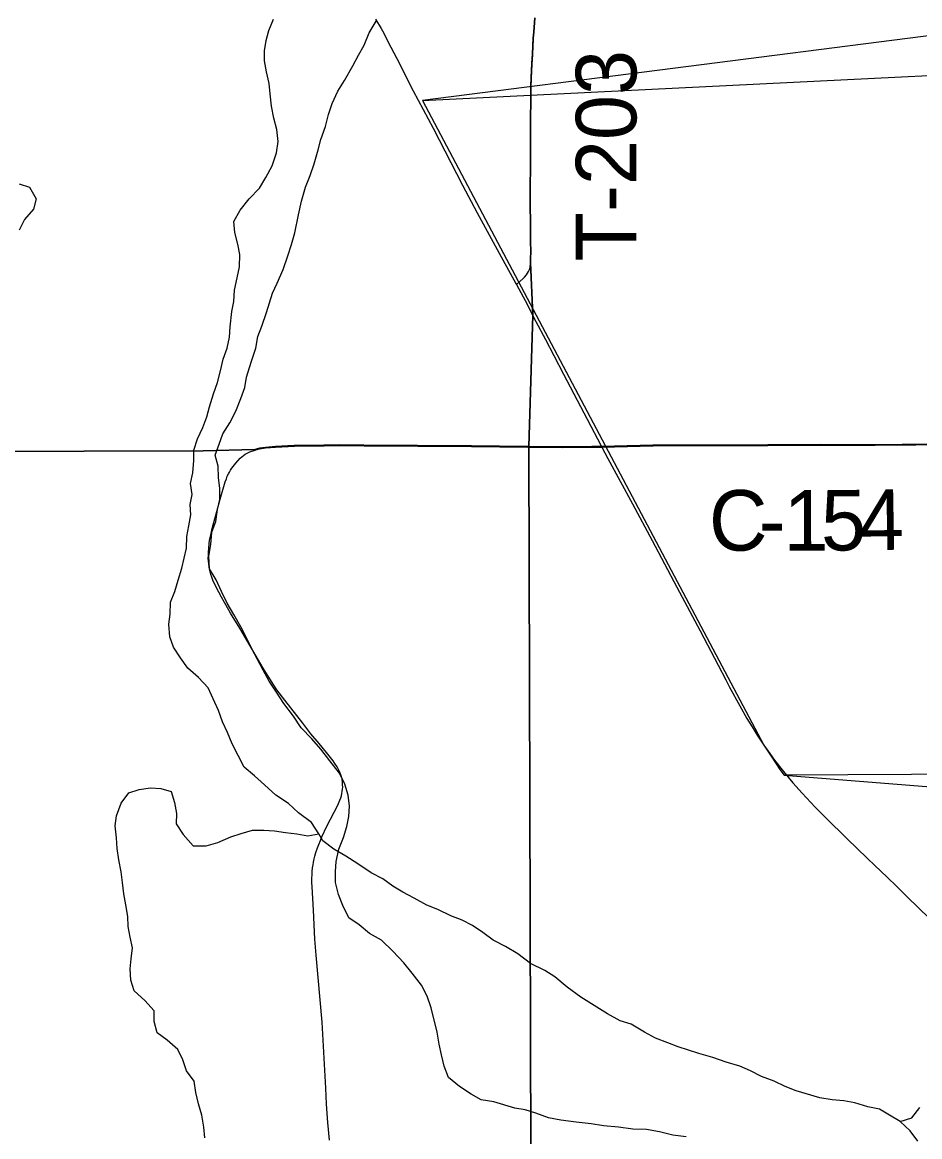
# Model space of a CAD drawing. Extents: x 0 to 34, y 0 to 22.
# Drawn here: x 4.562 to 5.404, y 16.57 to 17.616 of the extents above; entities that cross this region are included whole.
import ezdxf

# ---------------------------------------------------------------- set-up
doc = ezdxf.new("R2010")
doc.units = 0
for name, color, linetype in [('GM_X_Corporation', 7, 'Continuous'), ('GM_X_County_Road', 7, 'Continuous'), ('GM_X_County_Road_Text', 7, 'Continuous'), ('GM_X_Major_Lake', 7, 'Continuous'), ('GM_X_Minor_River', 7, 'Continuous'), ('GM_X_State_Location', 7, 'Continuous'), ('GM_X_State_Route', 7, 'Continuous'), ('GM_X_Township_Road', 7, 'Continuous'), ('GM_X_Township_Road_Text', 7, 'Continuous'), ('SH_Data', 7, 'Continuous'), ('SH_Text', 7, 'Continuous')]:
    doc.layers.add(name, color=color, linetype=linetype)

msp = doc.modelspace()

# ---------------------------------------------------------------- linework, layer by layer
at = {"layer": 'GM_X_Corporation'}
for points in [[(3.7259, 17.2107), (4.732, 17.2135), (4.7806, 17.215), (4.7848, 17.216), (4.7904, 17.2169), (4.7998, 17.2177), (4.8174, 17.2186), (4.8453, 17.219), (4.8603, 17.2191), (4.8829, 17.219), (4.9837, 17.2182), (5.0256, 17.2178), (5.0375, 17.2177), (5.0413, 17.3408), (5.0391, 17.3902), (5.0393, 17.3938), (5.0394, 17.4007), (5.0393, 17.4099), (5.0392, 17.4217), (5.0391, 17.4308), (5.039, 17.441), (5.039, 17.4504), (5.039, 17.4575), (5.039, 17.4661), (5.0391, 17.4754), (5.0392, 17.4846), (5.0392, 17.4911), (5.0392, 17.5272), (5.0394, 17.5401), (5.0396, 17.5554), (5.0398, 17.5638), (5.0404, 17.5771), (5.041, 17.586), (5.0414, 17.5935), (5.0418, 17.6007), (5.0422, 17.6065), (5.0432, 17.6198)], [(3.7259, 17.2107), (4.732, 17.2135), (4.7806, 17.215), (4.7848, 17.216), (4.7904, 17.2169), (4.7998, 17.2177), (4.8174, 17.2186), (4.8453, 17.219), (4.8603, 17.2191), (4.8829, 17.219), (4.9837, 17.2182), (5.0364, 17.2177), (5.0375, 17.2177), (5.0413, 17.3408), (5.0391, 17.3902), (5.0393, 17.3938), (5.0394, 17.4007), (5.0393, 17.4099), (5.0392, 17.4217), (5.0391, 17.4308), (5.039, 17.441), (5.039, 17.4504), (5.039, 17.4575), (5.039, 17.4661), (5.0391, 17.4754), (5.0392, 17.4846), (5.0392, 17.4911), (5.0392, 17.5272), (5.0394, 17.5401), (5.0396, 17.5554), (5.0398, 17.5638), (5.0404, 17.5771), (5.041, 17.586), (5.0414, 17.5935), (5.0418, 17.6007), (5.0422, 17.6065), (5.0432, 17.6198)], [(5.0432, 17.6198), (5.0422, 17.6065), (5.0418, 17.6007), (5.0414, 17.5935), (5.041, 17.586), (5.0404, 17.5771), (5.0398, 17.5638), (5.0396, 17.5554), (5.0394, 17.5401), (5.0392, 17.5272), (5.0392, 17.4911), (5.0392, 17.4846), (5.0391, 17.4754), (5.039, 17.4661), (5.039, 17.4575), (5.039, 17.4504), (5.039, 17.441), (5.0391, 17.4308), (5.0392, 17.4217), (5.0393, 17.4099), (5.0394, 17.4007), (5.0393, 17.3938), (5.0391, 17.3902), (5.0413, 17.3408), (5.0375, 17.2177), (5.0688, 17.2173), (5.0967, 17.2176), (5.1058, 17.2177), (5.154, 17.2188), (5.217, 17.219), (5.2617, 17.2192), (5.2822, 17.2193), (5.3114, 17.2196), (5.3388, 17.2194), (5.3623, 17.2194), (5.4388, 17.2202)], [(5.4388, 17.2202), (5.3623, 17.2194), (5.3388, 17.2194), (5.3114, 17.2196), (5.2822, 17.2193), (5.2617, 17.2192), (5.217, 17.219), (5.154, 17.2188), (5.1058, 17.2177), (5.0967, 17.2176), (5.0688, 17.2173), (5.0375, 17.2177), (5.0375, 17.2161), (5.0398, 16.4459)], [(2.114, 13.8173), (5.0539, 13.8173), (5.0552, 14.1423), (5.0521, 14.2095), (5.0518, 14.2807), (5.0535, 14.3223), (5.0506, 14.4841), (5.0493, 14.6873), (5.0428, 16.1022), (5.0398, 16.4459), (5.0375, 17.2161), (5.0375, 17.2177), (5.0364, 17.2177), (4.9837, 17.2182), (4.8829, 17.219), (4.8603, 17.2191), (4.8453, 17.219), (4.8174, 17.2186), (4.7998, 17.2177), (4.7904, 17.2169), (4.7848, 17.216), (4.7806, 17.215), (4.732, 17.2135), (3.7259, 17.2107)]]:
    msp.add_lwpolyline(points, dxfattribs=at)
at = {"layer": 'GM_X_County_Road'}
for points in [[(5.106, 17.2172), (5.1542, 17.2182), (5.2172, 17.2185), (5.2619, 17.2186), (5.2824, 17.2188), (5.3116, 17.219), (5.339, 17.2188), (5.3625, 17.2189), (5.439, 17.2196)], [(4.8505, 16.5668), (4.849, 16.5835), (4.8478, 16.6008), (4.8471, 16.6157), (4.8437, 16.6777), (4.838, 16.7406), (4.8369, 16.7555), (4.8354, 16.7828), (4.8342, 16.8045), (4.8341, 16.8087), (4.8341, 16.8126), (4.8342, 16.8157), (4.8343, 16.8189), (4.8347, 16.8224), (4.8351, 16.8251), (4.8356, 16.8278), (4.8361, 16.8307), (4.8369, 16.8334), (4.8378, 16.8368), (4.8393, 16.8411), (4.8404, 16.8444), (4.842, 16.8482), (4.8433, 16.8514), (4.8482, 16.8615), (4.8585, 16.8813), (4.8604, 16.8858), (4.8611, 16.888), (4.8618, 16.8899), (4.8622, 16.892), (4.8626, 16.894), (4.8628, 16.8962), (4.863, 16.8982), (4.8629, 16.9003), (4.8628, 16.9025), (4.8623, 16.906), (4.8613, 16.9095), (4.86, 16.9129), (4.8587, 16.9153), (4.8577, 16.9172), (4.8556, 16.9203), (4.8539, 16.9228), (4.8479, 16.9306), (4.8409, 16.939), (4.833, 16.9482), (4.8254, 16.9581), (4.8086, 16.9796), (4.8013, 16.9895), (4.7978, 16.9947), (4.7951, 16.9988), (4.7909, 17.0056), (4.7883, 17.0098), (4.7663, 17.0471), (4.7578, 17.0612), (4.7492, 17.0763), (4.7443, 17.0856), (4.7412, 17.0924), (4.7402, 17.0952), (4.7393, 17.0977), (4.7386, 17.1002), (4.738, 17.1026), (4.7376, 17.1047), (4.7372, 17.1076), (4.737, 17.1104), (4.7368, 17.1126), (4.7369, 17.1154), (4.7369, 17.1182), (4.7373, 17.1223), (4.7377, 17.1266), (4.7381, 17.1294), (4.7386, 17.1322), (4.7395, 17.1362), (4.7406, 17.1407), (4.7438, 17.1533), (4.7479, 17.1684), (4.7527, 17.1845), (4.7538, 17.1873), (4.7547, 17.1898), (4.7558, 17.1919), (4.7566, 17.1937), (4.7578, 17.1956), (4.759, 17.1975), (4.7626, 17.2021), (4.7667, 17.2066), (4.7713, 17.2105), (4.7757, 17.2127), (4.7808, 17.2144), (4.7816, 17.2146)], [(4.7816, 17.2146), (4.785, 17.2155), (4.7906, 17.2164), (4.8, 17.2171), (4.8176, 17.2181), (4.8456, 17.2184), (4.8605, 17.2186), (4.8831, 17.2184), (4.9839, 17.2176), (5.0366, 17.2171), (5.0377, 17.2171)], [(5.0377, 17.2171), (5.069, 17.2168), (5.0969, 17.2171), (5.106, 17.2172)]]:
    msp.add_lwpolyline(points, dxfattribs=at)
at = {"layer": 'GM_X_Major_Lake'}
for points in [[(4.655, 16.883), (4.6622, 16.8929), (4.672, 16.896), (4.6826, 16.8976), (4.6924, 16.8969), (4.7019, 16.8939), (4.705, 16.8837), (4.707, 16.8735), (4.7067, 16.8636), (4.7132, 16.8538), (4.7227, 16.8429), (4.7348, 16.843), (4.7458, 16.8461), (4.7579, 16.8515), (4.7677, 16.8546), (4.7782, 16.8577), (4.7888, 16.8578), (4.7991, 16.8572), (4.8093, 16.8557), (4.8199, 16.8543), (4.8301, 16.8525), (4.8407, 16.8544), (4.8338, 16.865), (4.8216, 16.874), (4.8121, 16.8827), (4.8003, 16.8905), (4.7896, 16.9003), (4.7801, 16.9086), (4.7706, 16.9168), (4.7591, 16.9388), (4.7548, 16.9493), (4.7502, 16.9595), (4.7463, 16.9701), (4.7413, 16.9811), (4.7367, 16.9913), (4.7275, 17.0011), (4.7176, 17.0097), (4.7107, 17.0195), (4.7042, 17.0293), (4.7008, 17.0392), (4.6999, 17.0509), (4.701, 17.0604), (4.7013, 17.0718), (4.7053, 17.0817), (4.7087, 17.0923), (4.712, 17.1034), (4.7164, 17.1223), (4.7167, 17.1333), (4.7185, 17.1432), (4.7203, 17.1535), (4.7198, 17.1633), (4.7217, 17.1728), (4.7201, 17.1831), (4.7223, 17.1929), (4.7233, 17.2047), (4.7232, 17.2142), (4.7266, 17.2248), (4.7318, 17.2355), (4.7355, 17.2454), (4.7381, 17.2549), (4.7417, 17.267), (4.7454, 17.2777), (4.7484, 17.2887), (4.7509, 17.2997), (4.7547, 17.31), (4.7568, 17.3202), (4.7575, 17.3301), (4.7589, 17.3442), (4.7607, 17.3536), (4.7614, 17.3643), (4.764, 17.376), (4.7662, 17.3863), (4.7665, 17.3977), (4.7645, 17.4075), (4.7618, 17.4185), (4.7609, 17.4287), (4.7669, 17.4394), (4.7751, 17.4501), (4.7849, 17.46), (4.7909, 17.4699), (4.7968, 17.481), (4.8009, 17.4931), (4.8023, 17.5038), (4.8011, 17.5151), (4.7984, 17.5257), (4.796, 17.5371), (4.7948, 17.5485), (4.794, 17.5583), (4.7916, 17.5693), (4.7896, 17.5795), (4.7896, 17.589), (4.791, 17.5985), (4.7936, 17.608), (4.798, 17.6187)], [(4.5593, 17.464), (4.5692, 17.461), (4.5753, 17.4501), (4.5727, 17.4402), (4.5645, 17.4306), (4.5593, 17.4207)], [(4.7336, 16.5692), (4.7327, 16.5791), (4.7308, 16.5904), (4.7277, 16.601), (4.7253, 16.6116), (4.7237, 16.6222), (4.7164, 16.632), (4.7129, 16.6422), (4.7083, 16.6521), (4.6984, 16.6607), (4.6889, 16.6675), (4.6862, 16.6781), (4.6861, 16.6883), (4.6773, 16.6981), (4.6674, 16.7071), (4.6643, 16.7169), (4.6635, 16.7276), (4.6645, 16.737), (4.6656, 16.7473), (4.6636, 16.7575), (4.6616, 16.7674), (4.6612, 16.7768), (4.6596, 16.7878), (4.6576, 16.798), (4.6564, 16.8086), (4.6552, 16.8185), (4.6528, 16.8299), (4.6512, 16.8405), (4.6508, 16.8507), (4.6495, 16.8617), (4.6506, 16.8712), (4.655, 16.883)]]:
    msp.add_lwpolyline(points, dxfattribs=at)
at = {"layer": 'GM_X_Minor_River'}
for points in [[(4.7938, 16.9974), (4.7884, 17.008), (4.783, 17.0178), (4.7773, 17.0284), (4.7727, 17.0382), (4.7673, 17.0484), (4.7608, 17.0601), (4.7546, 17.0707), (4.7492, 17.0816), (4.7442, 17.0926), (4.7381, 17.1028), (4.7372, 17.1149), (4.7391, 17.1256), (4.7401, 17.1373), (4.7438, 17.1472), (4.7456, 17.1586), (4.7478, 17.1681), (4.7477, 17.1783), (4.7465, 17.1886), (4.7461, 17.1992), (4.7433, 17.2094), (4.747, 17.22), (4.7504, 17.2296), (4.7571, 17.2398), (4.7627, 17.2509), (4.7675, 17.2627), (4.7712, 17.2729), (4.7727, 17.2828), (4.7771, 17.2969), (4.7815, 17.3098), (4.7833, 17.3208), (4.787, 17.3307), (4.7915, 17.3433), (4.797, 17.3615), (4.8015, 17.371), (4.8071, 17.3836), (4.8115, 17.3965), (4.8148, 17.4072), (4.8181, 17.4182), (4.8214, 17.4349), (4.8243, 17.4478), (4.828, 17.4611), (4.8325, 17.4718), (4.8362, 17.4828), (4.8399, 17.4961), (4.8424, 17.5056), (4.8469, 17.5178), (4.8495, 17.5292), (4.8532, 17.5394), (4.8584, 17.5512), (4.8647, 17.5611), (4.8726, 17.5749), (4.8778, 17.5848), (4.883, 17.5943), (4.8878, 17.6057), (4.8942, 17.6167)], [(5.1851, 16.57), (5.1726, 16.5715), (5.1601, 16.5748), (5.1479, 16.577), (5.1351, 16.5772), (5.1218, 16.579), (5.1078, 16.5804), (5.0961, 16.5822), (5.082, 16.5837), (5.0676, 16.5858), (5.0559, 16.588), (5.0441, 16.5921), (5.0343, 16.5954), (5.0244, 16.5969), (5.0047, 16.6028), (4.9929, 16.6046), (4.9834, 16.6102), (4.9724, 16.6173), (4.9621, 16.6256), (4.9582, 16.6362), (4.9555, 16.6471), (4.9535, 16.657), (4.9516, 16.6683), (4.9461, 16.6911), (4.9422, 16.702), (4.9368, 16.7122), (4.928, 16.7235), (4.9204, 16.7333), (4.9101, 16.7442), (4.8994, 16.7544), (4.888, 16.7608), (4.8785, 16.769), (4.8686, 16.7754), (4.8632, 16.7871), (4.859, 16.7973), (4.8562, 16.8087), (4.8561, 16.8189), (4.8568, 16.8284), (4.8594, 16.8398), (4.8638, 16.8508), (4.8668, 16.8611), (4.8686, 16.8706), (4.8693, 16.8804), (4.8681, 16.8907), (4.865, 16.9009), (4.86, 16.9111), (4.8508, 16.9228), (4.8424, 16.9337), (4.834, 16.9435), (4.824, 16.9537), (4.8168, 16.9646), (4.8076, 16.9767), (4.8007, 16.9872), (4.7938, 16.9974)], [(5.3859, 16.5845), (5.3761, 16.5905), (5.3665, 16.5961), (5.3556, 16.5983), (5.3434, 16.602), (5.3332, 16.6038), (5.3222, 16.6048), (5.3105, 16.6066), (5.2884, 16.6133), (5.2782, 16.6174), (5.2679, 16.6222), (5.2558, 16.6267), (5.2455, 16.6319), (5.2357, 16.6364), (5.2228, 16.6401), (5.2102, 16.6446), (5.197, 16.6482), (5.1776, 16.6545), (5.1681, 16.6583), (5.1564, 16.6627), (5.1461, 16.6683), (5.1335, 16.6758), (5.1233, 16.6788), (5.1115, 16.6855), (5.0864, 16.7012), (5.0735, 16.7106), (5.062, 16.72), (5.0525, 16.726), (5.0392, 16.7327), (5.0274, 16.7417), (5.0156, 16.7485), (5.0042, 16.7545), (4.9943, 16.7616), (4.9848, 16.7683), (4.975, 16.7732), (4.9643, 16.7773), (4.9522, 16.7832), (4.9419, 16.7873), (4.9301, 16.7941), (4.9195, 16.7997), (4.91, 16.8053), (4.9005, 16.812), (4.8898, 16.8177), (4.8773, 16.8263), (4.8659, 16.8334), (4.8545, 16.8398), (4.8442, 16.8476), (4.8407, 16.8544)], [(5.3859, 16.5845), (5.3969, 16.588), (5.4044, 16.5975)], [(5.4027, 16.566), (5.3955, 16.5758), (5.3859, 16.5845)]]:
    msp.add_lwpolyline(points, dxfattribs=at)
at = {"layer": 'GM_X_State_Route'}
for points in [[(4.8938, 17.6187), (4.899, 17.6099), (4.9002, 17.6075), (4.9081, 17.5923), (4.9136, 17.5816)], [(4.9136, 17.5816), (4.9291, 17.5513), (4.9477, 17.5162), (4.9754, 17.4628), (4.989, 17.4369), (5.0097, 17.399), (5.0254, 17.3706)], [(5.0254, 17.3706), (5.0259, 17.3697), (5.0362, 17.3505), (5.0415, 17.3403)], [(5.0415, 17.3403), (5.0442, 17.3351), (5.0532, 17.318), (5.0609, 17.3031), (5.0701, 17.2855), (5.086, 17.2552), (5.1019, 17.2249), (5.106, 17.2172)], [(5.106, 17.2172), (5.1118, 17.2063), (5.1349, 17.1639), (5.1533, 17.1294), (5.1765, 17.0858), (5.1985, 17.0446), (5.2153, 17.0124), (5.2223, 16.9989)], [(5.2223, 16.9989), (5.226, 16.9918), (5.2355, 16.9744), (5.2422, 16.9625), (5.247, 16.9547), (5.2519, 16.9468), (5.2582, 16.9375), (5.2638, 16.9296), (5.2682, 16.9235), (5.2766, 16.9128), (5.2854, 16.9023), (5.294, 16.8925), (5.3063, 16.8794), (5.3163, 16.8693), (5.3363, 16.8497), (5.355, 16.8315), (5.3622, 16.8246), (5.3739, 16.8135), (5.3828, 16.8048), (5.3926, 16.7953), (5.4136, 16.7749)]]:
    msp.add_lwpolyline(points, dxfattribs=at)
at = {"layer": 'GM_X_Township_Road'}
for points in [[(5.0393, 17.3896), (5.0395, 17.3932), (5.0396, 17.4001), (5.0395, 17.4094), (5.0394, 17.4211), (5.0393, 17.4302), (5.0393, 17.4404), (5.0392, 17.4499), (5.0392, 17.457), (5.0393, 17.4656), (5.0393, 17.4748), (5.0394, 17.484), (5.0394, 17.4905), (5.0394, 17.5266), (5.0396, 17.5395), (5.0398, 17.5549), (5.0401, 17.5633), (5.0406, 17.5765), (5.0412, 17.5854), (5.0416, 17.593), (5.042, 17.6002), (5.0424, 17.606), (5.0434, 17.6192)], [(5.0259, 17.3697), (5.0322, 17.3753), (5.0336, 17.3767), (5.0354, 17.3788), (5.0364, 17.3802), (5.0374, 17.3819), (5.0382, 17.3838), (5.0387, 17.3855), (5.039, 17.3872), (5.0391, 17.3884), (5.0393, 17.3896)]]:
    msp.add_lwpolyline(points, dxfattribs=at)
at = {"layer": 'SH_Data'}
msp.add_lwpolyline([(4.9378, 17.5422), (5.2582, 16.9375), (5.2655, 16.9262), (5.273, 16.9147), (5.2772, 16.9092)], dxfattribs=at)
at = {"layer": 'SH_Text'}
for points in [[(9.4006, 18.113), (4.9378, 17.5422), (9.4006, 17.763)], [(9.4006, 16.931), (5.2772, 16.9092), (9.4006, 16.581)]]:
    msp.add_lwpolyline(points, close=True, dxfattribs=at)

# ---------------------------------------------------------------- texts
at = {"layer": 'GM_X_County_Road_Text'}
for s, rotation, p in [('C', 0, (5.2066, 17.12)), ('1', 0.0545, (5.2767, 17.12)), ('5', 0.2253, (5.3118, 17.1201)), ('4', 0.9903, (5.3477, 17.1202)), ('-', 0.0117, (5.2533, 17.12))]:
    msp.add_text(s, height=0.0568, rotation=rotation, dxfattribs=at).set_placement(p)
at = {"layer": 'GM_X_State_Location'}
msp.add_text('14', height=0.000189, rotation=0, dxfattribs=at).set_placement((5.3583, 16.7465))
at = {"layer": 'GM_X_Township_Road_Text'}
msp.add_text('T-203', height=0.05682, rotation=90, dxfattribs=at).set_placement((5.1385, 17.3912))

doc.saveas('drawing.dxf')
